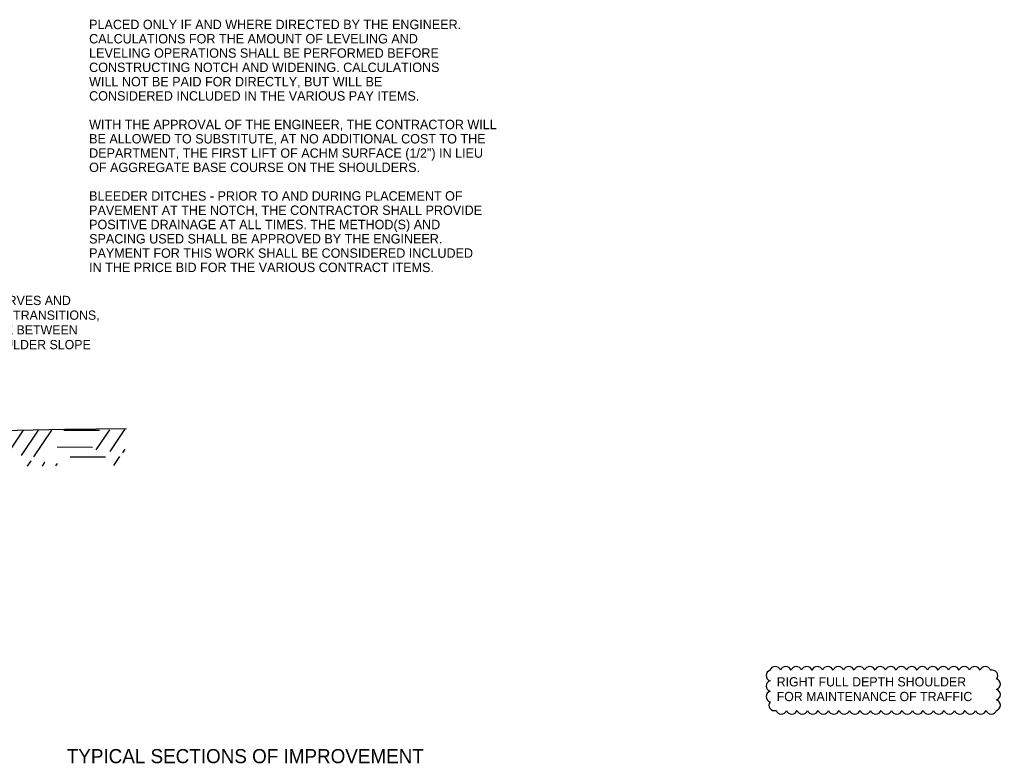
# Model space of a CAD drawing. Extents: x 1398183 to 1398373, y 1967240 to 1968889.
# Drawn here: x 1398305.2 to 1398367.8, y 1967860.8 to 1967908.3 of the extents above; entities that cross this region are included whole.
import ezdxf

# ---------------------------------------------------------------- set-up
doc = ezdxf.new("R2010")
doc.units = 0
for name, color, linetype in [('19', 7, 'Continuous'), ('42', 7, 'Continuous'), ('60', 7, 'Continuous'), ('9', 7, 'Continuous')]:
    doc.layers.add(name, color=color, linetype=linetype)

msp = doc.modelspace()

# ---------------------------------------------------------------- linework, layer by layer
at = {"layer": '19'}
for centre, radius, start, end in [((1398353.456, 1967866.665), 0.352, 17.5, 162.5), ((1398354.127, 1967866.665), 0.352, 17.5, 162.5), ((1398354.798, 1967866.665), 0.352, 17.5, 162.5), ((1398355.469, 1967866.665), 0.352, 17.5, 162.5), ((1398356.139, 1967866.665), 0.352, 17.5, 162.5), ((1398356.81, 1967866.665), 0.352, 17.5, 162.5), ((1398357.481, 1967866.665), 0.352, 17.5, 162.5), ((1398358.151, 1967866.665), 0.352, 17.5, 162.5), ((1398358.822, 1967866.665), 0.352, 17.5, 162.5), ((1398359.493, 1967866.665), 0.352, 17.5, 162.5), ((1398360.163, 1967866.665), 0.352, 17.5, 162.5), ((1398360.834, 1967866.665), 0.352, 17.5, 162.5), ((1398361.505, 1967866.665), 0.352, 17.5, 162.5), ((1398362.175, 1967866.665), 0.352, 17.5, 162.5), ((1398362.846, 1967866.665), 0.352, 17.5, 162.5), ((1398363.517, 1967866.665), 0.352, 17.5, 162.5), ((1398364.188, 1967866.665), 0.352, 17.5, 162.5), ((1398364.858, 1967866.665), 0.352, 17.5, 162.5), ((1398365.529, 1967866.665), 0.352, 17.5, 162.5), ((1398366.2, 1967866.665), 0.352, 17.5, 162.5), ((1398366.87, 1967866.665), 0.352, 17.5, 162.5), ((1398353.227, 1967866.435), 0.352, 107.5, 252.5), ((1398367.311, 1967866.435), 0.351, 322.43874, 107.43874), ((1398353.227, 1967865.765), 0.352, 107.5, 252.5), ((1398367.484, 1967865.886), 0.352, 287.5, 72.5), ((1398353.227, 1967865.094), 0.352, 107.5, 252.5), ((1398367.484, 1967865.215), 0.352, 287.5, 72.5), ((1398353.4, 1967864.544), 0.351, 142.43874, 287.43874), ((1398367.484, 1967864.544), 0.352, 287.5, 72.5), ((1398353.84, 1967864.315), 0.352, 197.5, 342.5), ((1398354.511, 1967864.315), 0.352, 197.5, 342.5), ((1398355.182, 1967864.315), 0.352, 197.5, 342.5), ((1398355.852, 1967864.315), 0.352, 197.5, 342.5), ((1398356.523, 1967864.315), 0.352, 197.5, 342.5), ((1398357.194, 1967864.315), 0.352, 197.5, 342.5), ((1398357.864, 1967864.315), 0.352, 197.5, 342.5), ((1398358.535, 1967864.315), 0.352, 197.5, 342.5), ((1398359.206, 1967864.315), 0.352, 197.5, 342.5), ((1398359.877, 1967864.315), 0.352, 197.5, 342.5), ((1398360.547, 1967864.315), 0.352, 197.5, 342.5), ((1398361.218, 1967864.315), 0.352, 197.5, 342.5), ((1398361.889, 1967864.315), 0.352, 197.5, 342.5), ((1398362.559, 1967864.315), 0.352, 197.5, 342.5), ((1398363.23, 1967864.315), 0.352, 197.5, 342.5), ((1398363.901, 1967864.315), 0.352, 197.5, 342.5), ((1398364.571, 1967864.315), 0.352, 197.5, 342.5), ((1398365.242, 1967864.315), 0.352, 197.5, 342.5), ((1398365.913, 1967864.315), 0.352, 197.5, 342.5), ((1398366.583, 1967864.315), 0.352, 197.5, 342.5), ((1398367.254, 1967864.315), 0.352, 197.5, 342.5)]:
    msp.add_arc(centre, radius, start, end, dxfattribs=at)
at = {"layer": '42'}
msp.add_lwpolyline([(1398301.963, 1967882.034), (1398308.072, 1967882.173), (1398312.019, 1967882.22)], dxfattribs=at)
at = {"layer": '9'}
for p, q in [((1398305.422, 1967882.102), (1398304.399, 1967880.568)), ((1398306.374, 1967882.108), (1398305.289, 1967880.48)), ((1398307.234, 1967882.112), (1398306.087, 1967880.392)), ((1398310.287, 1967882.085), (1398308.025, 1967882.091)), ((1398310.932, 1967882.133), (1398310.071, 1967880.841)), ((1398311.885, 1967882.138), (1398310.961, 1967880.753)), ((1398309.848, 1967881.007), (1398307.586, 1967881.013)), ((1398311.913, 1967880.896), (1398311.759, 1967880.665)), ((1398305.903, 1967880.15), (1398305.676, 1967879.809)), ((1398310.685, 1967880.381), (1398308.423, 1967880.386)), ((1398311.575, 1967880.423), (1398311.187, 1967879.84)), ((1398306.794, 1967880.062), (1398306.629, 1967879.815)), ((1398307.591, 1967879.974), (1398307.489, 1967879.819))]:
    msp.add_line(p, q, dxfattribs=at)

# ---------------------------------------------------------------- texts
at = {"layer": '19'}
for s, height, p in [('PLACED ONLY IF AND WHERE DIRECTED BY THE ENGINEER.', 0.6, (1398309.634, 1967907.713)), ('CALCULATIONS FOR THE AMOUNT OF LEVELING AND', 0.6, (1398309.634, 1967906.801)), ('LEVELING OPERATIONS SHALL BE PERFORMED BEFORE ', 0.6, (1398309.634, 1967905.888)), ('CONSTRUCTING NOTCH AND WIDENING. CALCULATIONS', 0.6, (1398309.634, 1967904.976)), ('WILL NOT BE PAID FOR DIRECTLY, BUT WILL BE', 0.6, (1398309.634, 1967904.063)), ('CONSIDERED INCLUDED IN THE VARIOUS PAY ITEMS.', 0.6, (1398309.634, 1967903.151)), ('WITH THE APPROVAL OF THE ENGINEER, THE CONTRACTOR WILL', 0.6, (1398309.634, 1967901.326)), ('BE ALLOWED TO SUBSTITUTE, AT NO ADDITIONAL COST TO THE', 0.6, (1398309.634, 1967900.413)), ('DEPARTMENT, THE FIRST LIFT OF ACHM SURFACE (1/2") IN LIEU', 0.6, (1398309.634, 1967899.501)), ('OF AGGREGATE BASE COURSE ON THE SHOULDERS.', 0.6, (1398309.634, 1967898.588)), ('BLEEDER DITCHES - PRIOR TO AND DURING PLACEMENT OF', 0.6, (1398309.634, 1967896.763)), ('PAVEMENT AT THE NOTCH, THE CONTRACTOR SHALL PROVIDE', 0.6, (1398309.634, 1967895.851)), ('POSITIVE DRAINAGE AT ALL TIMES. THE METHOD(S) AND', 0.6, (1398309.634, 1967894.938)), ('SPACING USED SHALL BE APPROVED BY THE ENGINEER.', 0.6, (1398309.634, 1967894.026)), ('PAYMENT FOR THIS WORK SHALL BE CONSIDERED INCLUDED', 0.6, (1398309.634, 1967893.113)), ('IN THE PRICE BID FOR THE VARIOUS CONTRACT ITEMS.', 0.6, (1398309.634, 1967892.201)), ('ON ALL SUPERELEVATED CURVES AND', 0.59001, (1398293.207, 1967890.095)), ('THROUGH SUPERELEVATION TRANSITIONS,', 0.59001, (1398293.207, 1967889.155)), ('THE ALGEBRAIC DIFFERENCE BETWEEN', 0.59001, (1398293.207, 1967888.215)), ('PAVEMENT SLOPE AND SHOULDER SLOPE', 0.59001, (1398293.207, 1967887.275))]:
    msp.add_text(s, height=height, dxfattribs=at).set_placement(p)
at = {"layer": '42'}
for s, p in [('RIGHT FULL DEPTH SHOULDER', (1398353.547, 1967865.741)), ('FOR MAINTENANCE OF TRAFFIC', (1398353.547, 1967864.801))]:
    msp.add_text(s, height=0.59001, rotation=360, dxfattribs=at).set_placement(p)
at = {"layer": '60'}
msp.add_text('TYPICAL SECTIONS OF IMPROVEMENT', height=0.9, dxfattribs=at).set_placement((1398308.207, 1967860.839))

doc.saveas('drawing.dxf')
